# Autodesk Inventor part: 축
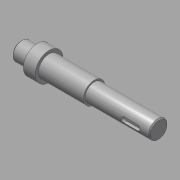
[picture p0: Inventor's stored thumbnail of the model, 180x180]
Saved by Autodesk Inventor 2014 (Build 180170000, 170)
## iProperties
Created: 2015-09
Part Number: 축
Material: 강철, 연강
Document SubType Name: Modeling
Designer: mduedu
Density: 1 g/cm^3
Appearance: 강철
Author: mduedu
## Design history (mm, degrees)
sketch "스케치1"
  geometry: L1 (-64, 0)-(64, 0); L2 (-64, 0)-(-64, 8.5); L3 (-64, 8.5)-(-49, 8.5); L4 (-49, 8.5)-(-49, 13); L5 (-49, 13)-(-38, 13); L6 (-38, 13)-(-38, 10); L7 (-38, 10)-(4, 10); L8 (4, 10)-(4, 8.5); L9 (4, 8.5)-(64, 8.5); L10 (64, 8.5)-(64, 0); 2 further points
  constraints: 20 end point, 5 parallel, 2 horizontal, 2 perpendicular, 1 coincident, 1 midpoint, 1 vertical
  dimensions: "d0" = 128 distance of L1.start L1.end; "d2" = 11 distance of L4.end L5.end; "d3" = 42 distance of L6.end L7.end; "d4" = 60 distance of L8.end L9.end; "d5" = 17 diameter of L3 L1; "d6" = 17 diameter of L9 L1; "d7" = 20 diameter of L7 L1; "d8" = 26 diameter of L5 L1
revolve "회전1" sketch "스케치1" stored, may be unused: angle "d9" = 90 deg
node "작업 평면1"
sketch "스케치2"
  geometry: L1 (5.5, 2.5)-(18.5, 2.5); L2 (18.5, -2.5)-(5.5, -2.5); L3 (5.5, 2.5)-(18.5, -2.5); L4 (18.5, 2.5)-(5.5, -2.5); L5 (30, -8.5)-(30, 8.5) reference; A1 r 2.5 centre (5.5, 0) between (5.5, 2.5) and (5.5, -2.5); A2 r 2.5 centre (18.5, 0) between (18.5, -2.5) and (18.5, 2.5); 2 further points
  constraints: 8 end point, 4 point on circle, 4 tangent, 2 centre point, 2 midpoint, 1 horizontal, 1 horizontal alignment, 1 parallel
  dimensions: "d10" = 18 dimension on A2 A1; "d12" = 9 distance edge to line of A2 L5; "d13" = 5 distance between parallel lines of L2 L1
extrude "돌출1" cut sketch "스케치2" distance "d14" = 3; taper "d15" = 0 deg
node "작업 평면2"
sketch "스케치4"
  geometry: L1 (7, -3)-(-9, -3); L2 (-9, 3)-(7, 3); L3 (-21, 10)-(-21, -10) reference; A1 r 3 centre (-9, 0) between (-9, 3) and (-9, -3); A2 r 3 centre (7, 0) between (7, -3) and (7, 3); 1 further point
  constraints: 4 end point, 4 point on circle, 4 tangent, 2 centre point, 1 horizontal, 1 horizontal alignment, 1 parallel
  dimensions: "d16" = 22 dimension on A1 A2; "d18" = 6 distance between parallel lines of L2 L1; "d19" = 9 distance edge to line of A1 L3
extrude "돌출2" cut sketch "스케치4" distance "d20" = 3.5; taper "d21" = 0 deg
sketch "스케치5"
  geometry: L1 (4, 8.5)-(64, 8.5) reference; L2 (4, -8.5)-(64, -8.5) reference; L3 (37, 8.5)-(37, -8.5); L4 (37, -6.5)-(35, -8.5); L5 (37, -8.5)-(35, -8.5); L6 (37, -8.5)-(37, -6.5); L7 (4, -10)-(4, 10) reference; 1 further point
  constraints: 8 end point, 4 point on line, 1 collinear, 1 perpendicular
  dimensions: "d22" = 4 diameter of L4.end L3; "d24" = 45 deg angle of L3 L4; "d26" = 33 distance between parallel lines of L3 L7
revolve "회전2" sketch "스케치5" stored, may be unused: angle "d27" = 90 deg
chamfer "모따기1" distance "d28" = 1; stored, may be unused: second distance "d29" = 2, angle "d30" = 45 deg
node "솔리드1"
